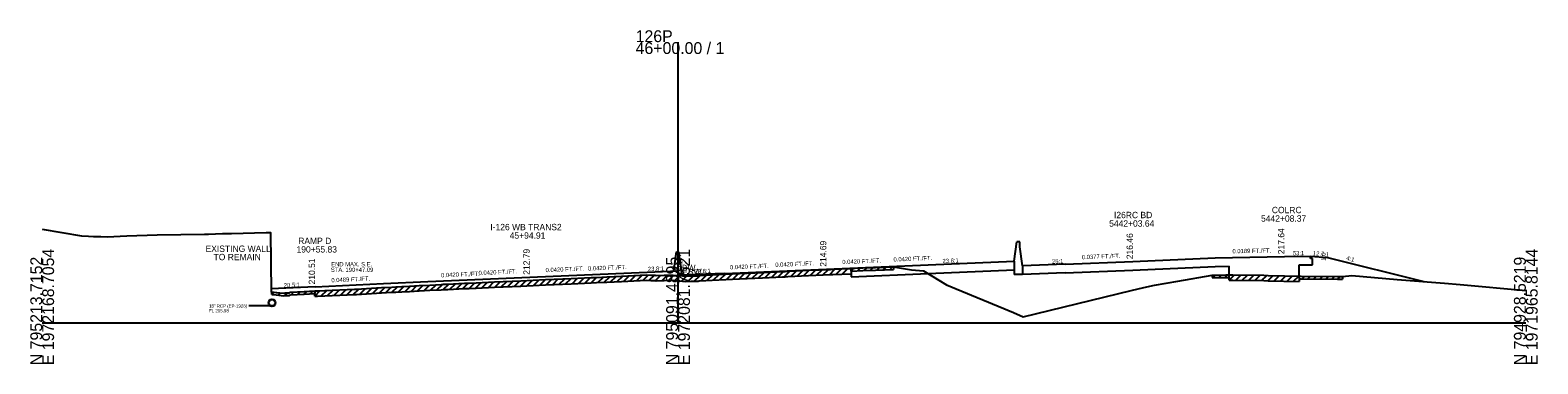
# Model space of a CAD drawing. Extents: x -161 to 1970889, y -4362 to 797231.
# Drawn here: x 997.2 to 1352.8, y 8490.3 to 8569.1 of the extents above; entities that cross this region are included whole.
import ezdxf

# ---------------------------------------------------------------- set-up
doc = ezdxf.new("R2010")
doc.units = 0
for name, color, linetype in [('RD_GPK_XS_Cell', 7, 'Continuous'), ('RD_XS_Base', 7, 'Continuous'), ('RD_XS_EarthShd', 7, 'Continuous'), ('RD_XS_ExGround', 7, 'Continuous'), ('RD_XS_ExPaveRet', 7, 'Continuous'), ('RD_XS_MedBWall', 7, 'Continuous'), ('RD_XS_Misc_Line', 7, 'Continuous'), ('RD_XS_Pave', 7, 'Continuous'), ('RD_XS_PaveOvlay', 7, 'Continuous'), ('RD_XS_PaveShd', 7, 'Continuous'), ('RD_XS_Pipe', 7, 'Continuous'), ('RD_XS_TieSlope', 7, 'Continuous'), ('RD_XS_TX_Elev_EX', 7, 'Continuous'), ('RD_XS_TX_Elev_PR', 7, 'Continuous'), ('RD_XS_TX_MkPT', 7, 'Continuous'), ('RD_XS_TX_Notes', 7, 'Continuous'), ('RD_XS_TX_Profile', 7, 'Continuous'), ('RD_XS_TX_ShdSlope', 7, 'Continuous'), ('RD_XS_TX_Slope', 7, 'Continuous'), ('RD_XS_TX_Station', 7, 'Continuous')]:
    doc.layers.add(name, color=color, linetype=linetype)

msp = doc.modelspace()

# ---------------------------------------------------------------- linework, layer by layer
at = {"layer": 'RD_GPK_XS_Cell'}
for p, q in [((1150, 8500), (1150, 8566.28)), ((1000, 8500), (1150, 8500)), ((1150, 8500), (1350, 8500))]:
    msp.add_line(p, q, dxfattribs=at)
at = {"layer": 'RD_XS_Base'}
for p, q in [((1299.17, 8515.2), (1299.17, 8515.76)), ((1299.68, 8515.21), (1299.17, 8515.2)), ((1299.68, 8513.73), (1299.68, 8515.21)), ((1190.84, 8510.9), (1209, 8511.66)), ((1209, 8511.66), (1229.29, 8512.51)), ((1241.3, 8511.81), (1231.3, 8511.41)), ((1241.3, 8511.81), (1257.31, 8512.42)), ((1257.31, 8512.42), (1276.75, 8513.29)), ((1276.75, 8513.29), (1280.04, 8513.35)), ((1296.57, 8513.67), (1299.68, 8513.73))]:
    msp.add_line(p, q, dxfattribs=at)
at = {"layer": 'RD_XS_EarthShd'}
msp.add_line((1299.17, 8515.76), (1303.25, 8515.44), dxfattribs=at)
at = {"layer": 'RD_XS_ExGround'}
msp.add_lwpolyline([(1000, 8522.09), (1009.26, 8520.56), (1010.91, 8520.47), (1012.09, 8520.35), (1013.87, 8520.36), (1015.29, 8520.33), (1019.93, 8520.51), (1027.11, 8520.76), (1038.26, 8520.95), (1039.2, 8520.97), (1042.54, 8521.06), (1043.76, 8521.09), (1044.63, 8521.11), (1052.81, 8521.3), (1053.26, 8521.3), (1053.88, 8521.3), (1054, 8507.31), (1055.19, 8507.2), (1056.98, 8507.03), (1057.31, 8507.05), (1058.33, 8507.08), (1058.61, 8507.24), (1061.8, 8507.39), (1064.92, 8507.58), (1073.66, 8507.92), (1074.17, 8507.95), (1080.08, 8508.31), (1082.47, 8508.46), (1083.41, 8508.49), (1084.82, 8508.54), (1086.64, 8508.66), (1088.95, 8508.81), (1091.46, 8508.93), (1094.15, 8509.08), (1094.63, 8509.15), (1095.31, 8509.15), (1095.66, 8509.14), (1099.62, 8509.33), (1100.73, 8509.38), (1102.36, 8509.46), (1106.7, 8509.66), (1112.91, 8509.92), (1118.74, 8510.23), (1120.77, 8510.31), (1124.8, 8510.47), (1129.51, 8510.69), (1130.74, 8510.74), (1133.23, 8510.86), (1136.67, 8511.02), (1138.16, 8511.09), (1142.48, 8511.3), (1143.55, 8511.28), (1144.61, 8511.25), (1144.87, 8511.2), (1146.72, 8511.24), (1148.87, 8511.29), (1150, 8511.19), (1150.4, 8511.15), (1151.67, 8511), (1153.1, 8511.07), (1154.72, 8511.11), (1154.96, 8511.17), (1156.52, 8511.28), (1158.02, 8511.36), (1164.53, 8511.66), (1169.95, 8511.89), (1174.61, 8512.1), (1175.31, 8512.12), (1175.88, 8512.16), (1180.74, 8512.4), (1185.98, 8512.63), (1186.52, 8512.66), (1193.6, 8512.97), (1196.61, 8513.07), (1200.84, 8513.2), (1205.11, 8512.5), (1207.94, 8512.24), (1213.34, 8508.95), (1229.12, 8502.46), (1231.39, 8501.42), (1256.87, 8507.62), (1259.89, 8508.32), (1262.39, 8508.86), (1267.91, 8509.85), (1275.97, 8511.29), (1279.24, 8511.32), (1279.79, 8511.32), (1280.88, 8511.31), (1288.21, 8511.22), (1289.25, 8511.2), (1297.03, 8511.02), (1305.61, 8510.92), (1306.74, 8510.91), (1308.92, 8511.17), (1319.62, 8510.25), (1330.83, 8509.38), (1334.52, 8509.08), (1350, 8507.67)], dxfattribs=at)
at = {"layer": 'RD_XS_ExPaveRet'}
for p, q in [((1186.52, 8511.41), (1190.84, 8511.6)), ((1190.84, 8512.85), (1190.84, 8511.6)), ((1190.84, 8512.23), (1190.84, 8512.85)), ((1190.84, 8512.23), (1193.6, 8512.35)), ((1193.6, 8512.35), (1196.61, 8512.44)), ((1196.61, 8512.44), (1200.84, 8512.57)), ((1200.84, 8513.2), (1200.84, 8512.57)), ((1095.66, 8507.89), (1099.62, 8508.08)), ((1099.62, 8508.08), (1100.73, 8508.13)), ((1100.73, 8508.13), (1102.36, 8508.21)), ((1102.36, 8508.21), (1106.7, 8508.41)), ((1106.7, 8508.41), (1112.91, 8508.67)), ((1112.91, 8508.67), (1118.74, 8508.98)), ((1118.74, 8508.98), (1120.77, 8509.06)), ((1120.77, 8509.06), (1124.8, 8509.22)), ((1124.8, 8509.22), (1129.51, 8509.44)), ((1129.51, 8509.44), (1130.74, 8509.49)), ((1130.74, 8509.49), (1133.23, 8509.61)), ((1133.23, 8509.61), (1136.67, 8509.77)), ((1136.67, 8509.77), (1138.16, 8509.84)), ((1138.16, 8509.84), (1142.48, 8510.05)), ((1142.48, 8510.05), (1143.55, 8510.03)), ((1143.55, 8510.03), (1144.61, 8510)), ((1144.61, 8510), (1144.87, 8509.95)), ((1144.87, 8509.95), (1146.72, 8509.99)), ((1146.72, 8509.99), (1148.87, 8510.04)), ((1148.87, 8510.04), (1150, 8509.94)), ((1150, 8509.94), (1150.4, 8509.9)), ((1150.4, 8509.9), (1151.67, 8509.75)), ((1151.67, 8509.75), (1153.1, 8509.82)), ((1153.1, 8509.82), (1154.72, 8509.86)), ((1154.72, 8509.86), (1154.96, 8509.92)), ((1154.96, 8509.92), (1156.52, 8510.03)), ((1156.52, 8510.03), (1158.02, 8510.11)), ((1158.02, 8510.11), (1164.53, 8510.41)), ((1164.53, 8510.41), (1169.95, 8510.64)), ((1169.95, 8510.64), (1174.61, 8510.85)), ((1174.61, 8510.85), (1175.31, 8510.87)), ((1175.31, 8510.87), (1175.88, 8510.91)), ((1175.88, 8510.91), (1180.74, 8511.15)), ((1180.74, 8511.15), (1185.98, 8511.38)), ((1185.98, 8511.38), (1186.52, 8511.41)), ((1275.97, 8511.29), (1275.97, 8510.67)), ((1280.04, 8510.07), (1280.04, 8511.32)), ((1280.04, 8510.7), (1280.04, 8511.32)), ((1280.04, 8510.07), (1280.88, 8510.06)), ((1280.88, 8510.06), (1288.21, 8509.97)), ((1288.21, 8509.97), (1289.25, 8509.95)), ((1289.25, 8509.95), (1296.57, 8509.78)), ((1296.57, 8511.03), (1296.57, 8509.78)), ((1296.57, 8511.03), (1296.57, 8510.4)), ((1306.74, 8510.91), (1306.74, 8510.28)), ((1054.16, 8506.67), (1054.16, 8507.3)), ((1054.16, 8506.67), (1055.19, 8506.58)), ((1055.19, 8506.58), (1056.98, 8506.4)), ((1056.98, 8506.4), (1057.31, 8506.42)), ((1057.31, 8506.42), (1058.33, 8506.46)), ((1058.33, 8506.46), (1058.61, 8506.62)), ((1058.61, 8506.62), (1061.8, 8506.77)), ((1061.8, 8506.77), (1064.28, 8506.92)), ((1064.28, 8506.29), (1064.28, 8507.54)), ((1064.28, 8507.54), (1064.28, 8506.92)), ((1064.28, 8506.29), (1064.92, 8506.33)), ((1064.92, 8506.33), (1073.66, 8506.67)), ((1073.66, 8506.67), (1074.17, 8506.7)), ((1074.17, 8506.7), (1080.08, 8507.06)), ((1080.08, 8507.06), (1082.47, 8507.21)), ((1082.47, 8507.21), (1083.41, 8507.24)), ((1083.41, 8507.24), (1084.82, 8507.29)), ((1084.82, 8507.29), (1086.64, 8507.41)), ((1086.64, 8507.41), (1088.95, 8507.56)), ((1088.95, 8507.56), (1091.46, 8507.68)), ((1091.46, 8507.68), (1094.15, 8507.83)), ((1094.15, 8507.83), (1094.63, 8507.9)), ((1094.63, 8507.9), (1095.31, 8507.9)), ((1095.31, 8507.9), (1095.66, 8507.89))]:
    msp.add_line(p, q, dxfattribs=at)
for points in [[(1275.97, 8510.67), (1279.24, 8510.7), (1279.79, 8510.7), (1280.04, 8510.7)], [(1296.57, 8510.4), (1297.02, 8510.39), (1305.6, 8510.29), (1306.74, 8510.28)]]:
    msp.add_lwpolyline(points, dxfattribs=at)
at = {"layer": 'RD_XS_MedBWall'}
for p, q in [((1229.29, 8514.55), (1229.96, 8519.1)), ((1230.63, 8519.1), (1229.96, 8519.1)), ((1230.63, 8517.92), (1230.63, 8519.1)), ((1149, 8512.21), (1149.67, 8516.76)), ((1149.67, 8516.76), (1150.18, 8516.76)), ((1151, 8511.26), (1150.18, 8516.76)), ((1231.3, 8513.45), (1230.63, 8517.92)), ((1229.29, 8514.55), (1229.29, 8511.41)), ((1231.3, 8513.45), (1231.3, 8511.41)), ((1231.3, 8511.41), (1229.29, 8511.41))]:
    msp.add_line(p, q, dxfattribs=at)
at = {"layer": 'RD_XS_Misc_Line'}
for p, q in [((1159.9, 8510.2), (1161.22, 8511.51)), ((1161.41, 8510.27), (1162.74, 8511.58)), ((1162.93, 8510.33), (1164.26, 8511.64)), ((1164.45, 8510.4), (1165.77, 8511.71)), ((1165.97, 8510.47), (1167.29, 8511.78)), ((1167.48, 8510.53), (1168.81, 8511.84)), ((1169, 8510.6), (1170.33, 8511.91)), ((1170.52, 8510.67), (1171.84, 8511.97)), ((1172.04, 8510.73), (1173.36, 8512.04)), ((1173.56, 8510.8), (1174.88, 8512.11)), ((1175.07, 8510.86), (1176.41, 8512.18)), ((1176.59, 8510.94), (1177.92, 8512.26)), ((1178.11, 8511.02), (1179.44, 8512.33)), ((1179.63, 8511.09), (1180.96, 8512.41)), ((1181.14, 8511.17), (1182.47, 8512.48)), ((1182.66, 8511.23), (1183.99, 8512.54)), ((1184.18, 8511.3), (1185.5, 8512.61)), ((1185.7, 8511.37), (1187.02, 8512.68)), ((1187.22, 8511.44), (1188.54, 8512.75)), ((1188.73, 8511.51), (1190.06, 8512.82)), ((1190.84, 8512.23), (1191.5, 8512.88)), ((1192.36, 8512.29), (1193.02, 8512.95)), ((1193.87, 8512.36), (1194.53, 8513)), ((1195.39, 8512.41), (1196.04, 8513.05)), ((1196.91, 8512.45), (1197.56, 8513.1)), ((1198.43, 8512.5), (1199.08, 8513.14)), ((1199.94, 8512.55), (1200.6, 8513.19)), ((1071.87, 8506.6), (1073.18, 8507.91)), ((1073.38, 8506.66), (1074.72, 8507.98)), ((1074.9, 8506.74), (1076.25, 8508.08)), ((1076.42, 8506.84), (1077.77, 8508.17)), ((1077.94, 8506.93), (1079.29, 8508.26)), ((1079.46, 8507.02), (1080.8, 8508.35)), ((1080.97, 8507.11), (1082.32, 8508.45)), ((1082.49, 8507.21), (1083.8, 8508.5)), ((1084.01, 8507.26), (1085.34, 8508.57)), ((1085.53, 8507.33), (1086.88, 8508.67)), ((1087.04, 8507.43), (1088.4, 8508.78)), ((1088.56, 8507.54), (1089.9, 8508.86)), ((1090.08, 8507.61), (1091.4, 8508.92)), ((1091.6, 8507.68), (1092.94, 8509.01)), ((1093.12, 8507.77), (1094.49, 8509.13)), ((1094.63, 8507.9), (1095.9, 8509.15)), ((1096.15, 8507.91), (1097.48, 8509.22)), ((1097.67, 8507.98), (1099, 8509.3)), ((1099.19, 8508.06), (1100.52, 8509.37)), ((1100.7, 8508.13), (1102.03, 8509.44)), ((1102.22, 8508.2), (1103.55, 8509.51)), ((1103.74, 8508.27), (1105.07, 8509.58)), ((1105.26, 8508.34), (1106.58, 8509.66)), ((1106.77, 8508.41), (1108.1, 8509.72)), ((1108.29, 8508.48), (1109.61, 8509.78)), ((1109.81, 8508.54), (1111.13, 8509.85)), ((1111.33, 8508.61), (1112.65, 8509.91)), ((1112.85, 8508.67), (1114.18, 8509.99)), ((1114.36, 8508.75), (1115.7, 8510.07)), ((1115.88, 8508.83), (1117.22, 8510.15)), ((1117.4, 8508.91), (1118.74, 8510.23)), ((1118.92, 8508.99), (1120.23, 8510.29)), ((1120.43, 8509.05), (1121.75, 8510.35)), ((1121.95, 8509.11), (1123.27, 8510.41)), ((1123.47, 8509.17), (1124.79, 8510.47)), ((1124.99, 8509.23), (1126.32, 8510.54)), ((1126.51, 8509.3), (1127.83, 8510.61)), ((1128.02, 8509.37), (1129.35, 8510.68)), ((1129.54, 8509.44), (1130.86, 8510.75)), ((1131.06, 8509.51), (1132.39, 8510.82)), ((1132.58, 8509.58), (1133.9, 8510.89)), ((1134.09, 8509.65), (1135.42, 8510.96)), ((1135.61, 8509.72), (1136.94, 8511.03)), ((1137.13, 8509.79), (1138.46, 8511.1)), ((1138.65, 8509.86), (1139.98, 8511.18)), ((1140.17, 8509.94), (1141.5, 8511.25)), ((1141.68, 8510.01), (1142.98, 8511.29)), ((1143.2, 8510.04), (1144.43, 8511.25)), ((1144.72, 8509.98), (1145.98, 8511.23)), ((1146.24, 8509.98), (1147.53, 8511.26)), ((1147.75, 8510.02), (1149.03, 8511.28)), ((1149.27, 8510.01), (1150.43, 8511.15)), ((1150.79, 8509.86), (1151.96, 8511.01)), ((1152.31, 8509.78), (1153.63, 8511.08)), ((1153.82, 8509.84), (1155.19, 8511.19)), ((1155.34, 8509.95), (1156.7, 8511.29)), ((1156.86, 8510.05), (1158.2, 8511.37)), ((1158.38, 8510.13), (1159.7, 8511.44)), ((1276.13, 8510.67), (1276.76, 8511.3)), ((1277.56, 8510.68), (1278.19, 8511.31)), ((1278.98, 8510.7), (1279.61, 8511.32)), ((1280.04, 8510.07), (1281.29, 8511.31)), ((1281.56, 8510.06), (1282.81, 8511.29)), ((1283.08, 8510.04), (1284.33, 8511.27)), ((1284.59, 8510.02), (1285.84, 8511.25)), ((1286.11, 8510), (1287.36, 8511.23)), ((1287.63, 8509.98), (1288.87, 8511.21)), ((1289.15, 8509.95), (1290.38, 8511.17)), ((1290.67, 8509.91), (1291.9, 8511.14)), ((1292.18, 8509.88), (1293.42, 8511.1)), ((1293.7, 8509.84), (1294.94, 8511.07)), ((1295.22, 8509.81), (1296.45, 8511.03)), ((1297.21, 8510.39), (1297.82, 8511.01)), ((1298.6, 8510.38), (1299.22, 8510.99)), ((1300, 8510.36), (1300.62, 8510.98)), ((1301.4, 8510.34), (1302.02, 8510.96)), ((1302.8, 8510.33), (1303.42, 8510.94)), ((1304.2, 8510.31), (1304.81, 8510.93)), ((1305.59, 8510.29), (1306.21, 8510.91)), ((1054.16, 8506.67), (1054.74, 8507.24)), ((1055.68, 8506.53), (1056.25, 8507.1)), ((1057.2, 8506.42), (1057.85, 8507.07)), ((1058.71, 8506.62), (1059.38, 8507.28)), ((1060.23, 8506.69), (1060.89, 8507.35)), ((1061.75, 8506.76), (1062.42, 8507.43)), ((1063.27, 8506.86), (1063.94, 8507.52)), ((1064.28, 8506.29), (1065.61, 8507.61)), ((1065.8, 8506.37), (1067.11, 8507.67)), ((1067.31, 8506.43), (1068.63, 8507.73)), ((1068.83, 8506.49), (1070.15, 8507.79)), ((1070.35, 8506.54), (1071.67, 8507.85))]:
    msp.add_line(p, q, dxfattribs=at)
at = {"layer": 'RD_XS_Pave'}
for p, q in [((1276.75, 8515.33), (1293.05, 8515.64)), ((1115, 8510.79), (1139, 8511.79)), ((1161, 8511.68), (1185, 8512.69)), ((1185, 8512.69), (1209, 8513.7)), ((1241.3, 8513.85), (1257.31, 8514.46)), ((1064.37, 8508.51), (1080.51, 8509.3)), ((1091, 8509.78), (1115, 8510.79))]:
    msp.add_line(p, q, dxfattribs=at)
at = {"layer": 'RD_XS_PaveOvlay'}
for p, q in [((1158.02, 8511.36), (1164.53, 8511.66)), ((1164.53, 8511.66), (1169.95, 8511.89)), ((1169.95, 8511.89), (1174.61, 8512.1)), ((1174.61, 8512.1), (1175.31, 8512.12)), ((1175.31, 8512.12), (1175.88, 8512.16)), ((1175.88, 8512.16), (1180.74, 8512.4)), ((1180.74, 8512.4), (1185.98, 8512.63)), ((1185.98, 8512.63), (1186.52, 8512.66)), ((1186.52, 8512.66), (1190.84, 8512.85)), ((1190.84, 8512.85), (1190.84, 8510.9)), ((1280.04, 8511.32), (1280.04, 8513.35)), ((1296.57, 8511.03), (1296.57, 8513.67)), ((1053.99, 8508), (1054, 8507.31)), ((1064.92, 8507.58), (1073.66, 8507.92)), ((1073.66, 8507.92), (1074.17, 8507.95)), ((1074.17, 8507.95), (1080.08, 8508.31)), ((1080.08, 8508.31), (1082.47, 8508.46)), ((1082.47, 8508.46), (1083.41, 8508.49)), ((1083.41, 8508.49), (1084.82, 8508.54)), ((1084.82, 8508.54), (1086.64, 8508.66)), ((1086.64, 8508.66), (1088.95, 8508.81)), ((1088.95, 8508.81), (1091.46, 8508.93)), ((1091.46, 8508.93), (1094.15, 8509.08)), ((1094.15, 8509.08), (1094.63, 8509.15)), ((1094.63, 8509.15), (1095.31, 8509.15)), ((1095.31, 8509.15), (1095.66, 8509.14)), ((1095.66, 8509.14), (1099.62, 8509.33)), ((1099.62, 8509.33), (1100.73, 8509.38)), ((1100.73, 8509.38), (1102.36, 8509.46)), ((1102.36, 8509.46), (1106.7, 8509.66)), ((1106.7, 8509.66), (1112.91, 8509.92)), ((1112.91, 8509.92), (1118.74, 8510.23)), ((1118.74, 8510.23), (1120.77, 8510.31)), ((1120.77, 8510.31), (1124.8, 8510.47)), ((1124.8, 8510.47), (1129.51, 8510.69)), ((1129.51, 8510.69), (1130.74, 8510.74)), ((1130.74, 8510.74), (1133.23, 8510.86)), ((1133.23, 8510.86), (1136.67, 8511.02)), ((1136.67, 8511.02), (1138.16, 8511.09)), ((1138.16, 8511.09), (1142.48, 8511.3)), ((1142.48, 8511.3), (1143.55, 8511.28)), ((1143.55, 8511.28), (1144.61, 8511.25)), ((1144.61, 8511.25), (1144.87, 8511.2)), ((1144.87, 8511.2), (1146.72, 8511.24)), ((1146.72, 8511.24), (1148.87, 8511.29)), ((1148.87, 8511.29), (1150, 8511.19)), ((1150, 8511.19), (1150.4, 8511.15)), ((1150.4, 8511.15), (1151.67, 8511)), ((1151.67, 8511), (1153.1, 8511.07)), ((1153.1, 8511.07), (1154.72, 8511.11)), ((1154.72, 8511.11), (1154.96, 8511.17)), ((1154.96, 8511.17), (1156.52, 8511.28)), ((1156.52, 8511.28), (1158.02, 8511.36)), ((1054, 8507.31), (1056.09, 8507.11)), ((1056.09, 8507.11), (1056.98, 8507.03)), ((1056.98, 8507.03), (1058.33, 8507.08)), ((1058.33, 8507.08), (1058.61, 8507.24)), ((1064.28, 8507.54), (1064.92, 8507.58))]:
    msp.add_line(p, q, dxfattribs=at)
for points in [[(1280.04, 8511.32), (1280.88, 8511.31), (1288.21, 8511.22), (1289.25, 8511.2), (1296.57, 8511.03)], [(1058.61, 8507.24), (1061.8, 8507.39), (1064.28, 8507.54)]]:
    msp.add_lwpolyline(points, dxfattribs=at)
at = {"layer": 'RD_XS_PaveShd'}
for p, q in [((1257.31, 8514.46), (1276.75, 8515.33)), ((1293.05, 8515.64), (1299.17, 8515.76)), ((1139, 8511.79), (1150, 8512.26)), ((1150, 8511.22), (1150, 8512.26)), ((1161, 8511.68), (1150, 8511.22)), ((1209, 8513.7), (1229.29, 8514.55)), ((1241.3, 8513.85), (1231.3, 8513.45)), ((1064.37, 8508.51), (1053.99, 8508)), ((1080.51, 8509.3), (1091, 8509.78))]:
    msp.add_line(p, q, dxfattribs=at)
at = {"layer": 'RD_XS_Pipe'}
msp.add_line((1053.71, 8503.98), (1048.71, 8503.98), dxfattribs=at)
for radius in [0.85, 0.75]:
    msp.add_circle((1054.21, 8504.73), radius, dxfattribs=at)
at = {"layer": 'RD_XS_TieSlope'}
msp.add_line((1303.25, 8515.44), (1325.97, 8509.76), dxfattribs=at)

# ---------------------------------------------------------------- texts
at = {"layer": 'RD_GPK_XS_Cell'}
for s, p in [('126P', (1140, 8566.28)), ('46+00.00 / 1', (1140, 8563.48))]:
    msp.add_text(s, height=2.8, dxfattribs=at).set_placement(p)
for s, p in [('N 795213.7152', (1000, 8490)), ('E 1972168.7054', (1002.8, 8490)), ('N 795091.4895', (1150, 8490)), ('E 1972081.7521', (1152.8, 8490)), ('N 794928.5219', (1350, 8490)), ('E 1971965.8144', (1352.8, 8490))]:
    msp.add_text(s, height=2.8, rotation=90, dxfattribs=at).set_placement(p)
at = {"layer": 'RD_XS_Pipe'}
for s, p in [('18" RCP (EP-1928)', (1039.36, 8503.6)), ('FL 205.98', (1039.36, 8502.48))]:
    msp.add_text(s, height=0.75, dxfattribs=at).set_placement(p)
at = {"layer": 'RD_XS_TX_Elev_EX'}
msp.add_text('213.19', height=1, rotation=90, dxfattribs=at).set_placement((1151, 8511.19))
at = {"layer": 'RD_XS_TX_Elev_PR'}
for s, p in [(' 217.64', (1293.05, 8515.64)), (' 214.69', (1185, 8512.69)), (' 216.46', (1257.31, 8514.46)), (' 210.51', (1064.37, 8508.51)), (' 212.79', (1115, 8510.79))]:
    msp.add_text(s, height=1.5, rotation=90, dxfattribs=at).set_placement(p)
at = {"layer": 'RD_XS_TX_MkPT'}
for s, p in [('WBW', (1149, 8512.21)), ('EBW', (1151, 8511.26))]:
    msp.add_text(s, height=1.5, dxfattribs=at).set_placement(p)
at = {"layer": 'RD_XS_TX_Notes'}
for s, height, p in [('EXISTING WALL', 1.5, (1038.54, 8516.75)), ('TO REMAIN', 1.5, (1040.43, 8514.79)), ('STA. 190+47.09', 1, (1068.1, 8512.03)), ('END MAX. S.E.', 1, (1068.18, 8513.34))]:
    msp.add_text(s, height=height, dxfattribs=at).set_placement(p)
at = {"layer": 'RD_XS_TX_Profile'}
for p in [(1212.41, 8514.09), (1142.91, 8512.21), (1153.91, 8511.64)]:
    msp.add_text('23.8:1', height=1, rotation=2.405, dxfattribs=at).set_placement(p)
at = {"layer": 'RD_XS_TX_ShdSlope'}
msp.add_text('12.7:1', height=1, rotation=355.512, dxfattribs=at).set_placement((1299.75, 8515.96))
at = {"layer": 'RD_XS_TX_Slope'}
for s, rotation, p in [('0.0420 FT./FT.', 2.405, (1188.77, 8513.85)), ('0.0420 FT./FT.', 2.405, (1200.85, 8514.45)), ('25:1', 2.289, (1238.24, 8513.98)), ('0.0377 FT./FT.', 2.1589, (1245.27, 8515)), ('0.0189 FT./FT.', 1.0815, (1280.8, 8516.41)), ('53:1', 1.0815, (1295.05, 8515.93)), ('1:0', 90, (1302.75, 8514.67)), ('4:1', 344.1175, (1307.58, 8514.89)), ('0.0420 FT./FT.', 2.405, (1094.11, 8510.74)), ('0.0420 FT./FT.', 2.405, (1102.96, 8511.28)), ('0.0420 FT./FT.', 2.405, (1118.77, 8511.95)), ('0.0420 FT./FT.', 2.405, (1128.77, 8512.32)), ('0.0420 FT./FT.', 2.405, (1162.28, 8512.61)), ('0.0420 FT./FT.', 2.405, (1172.96, 8513.19)), ('20.5:1', 2.7963, (1057.01, 8508.35)), ('0.0489 FT./FT.', 2.7969, (1068.24, 8509.54))]:
    msp.add_text(s, height=1, rotation=rotation, dxfattribs=at).set_placement(p)
at = {"layer": 'RD_XS_TX_Station'}
for s, p in [('I26RC BD', (1252.85, 8524.71)), ('COLRC', (1290.09, 8525.89)), ('I-126 WB TRANS2', (1105.72, 8521.87)), ('5442+03.64', (1251.71, 8522.71)), ('5442+08.37', (1287.54, 8523.89)), ('RAMP D', (1060.4, 8518.6)), ('45+94.91', (1110.29, 8519.87)), ('190+55.83', (1060, 8516.6))]:
    msp.add_text(s, height=1.5, dxfattribs=at).set_placement(p)

doc.saveas('drawing.dxf')
